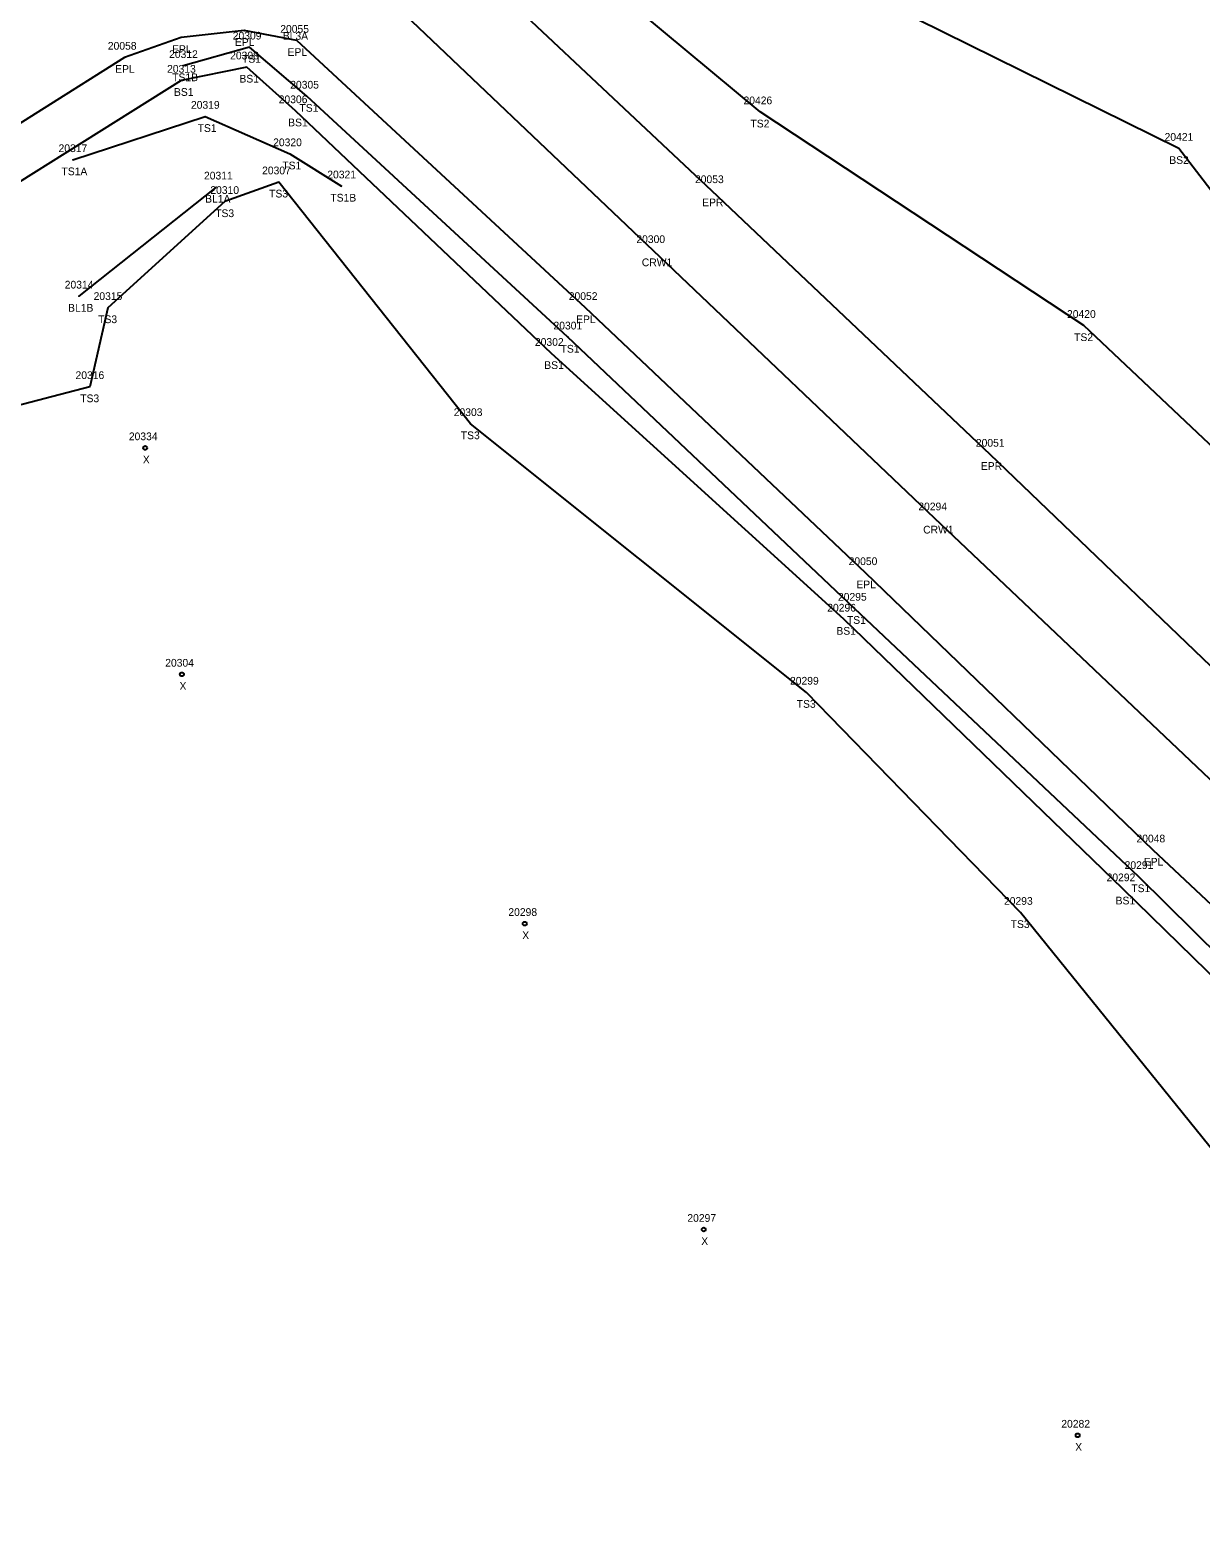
# Model space of a CAD drawing. Extents: x 1813127 to 1814107, y 1178171 to 1179078.
# Drawn here: x 1813803.8 to 1813955.3, y 1178426.8 to 1178622 of the extents above; entities that cross this region are included whole.
import ezdxf

# ---------------------------------------------------------------- set-up
doc = ezdxf.new("R2010")
doc.units = 0
for name, color, linetype in [('RD_DTM_BkLn1', 7, 'Continuous'), ('RD_DTM_BkLn2', 7, 'Continuous'), ('RD_EX_Road', 7, 'Continuous'), ('RD_EX_Road_txCode', 7, 'Continuous'), ('RD_SMD_Locator', 7, 'Continuous'), ('RD_SMD_Misc', 7, 'Continuous')]:
    doc.layers.add(name, color=color, linetype=linetype)

msp = doc.modelspace()

# ---------------------------------------------------------------- linework, layer by layer
at = {"layer": 'RD_DTM_BkLn1'}
msp.add_line((1813827.85, 1178601.7), (1813810.09, 1178587.58), dxfattribs=at)
msp.add_lwpolyline([(1814069.63, 1178419.56), (1814043.03, 1178443.95), (1814031.76, 1178453.98), (1813994.68, 1178489.07), (1813958.14, 1178523.5), (1813920.87, 1178558.86), (1813884.46, 1178593.47), (1813847.15, 1178628.98), (1813831.28, 1178643.33), (1813810.03, 1178662.5), (1813772.7, 1178693.86)], dxfattribs=at)
at = {"layer": 'RD_DTM_BkLn2'}
for points in [[(1814080.77, 1178431.89), (1814053.55, 1178456.53), (1814053.55, 1178456.53), (1814043.11, 1178466.04), (1814008.23, 1178502.68), (1813981.17, 1178545.08), (1813940.17, 1178583.78), (1813898.27, 1178611.44), (1813860.48, 1178642.94), (1813824.26, 1178675.11), (1813790.56, 1178704.96), (1813785.53, 1178702.33), (1813780.61, 1178703.45)], [(1814084.95, 1178436.37), (1814047.91, 1178471.1), (1814016.08, 1178513.45), (1813993.35, 1178553.48), (1813952.47, 1178606.71), (1813860.87, 1178652.01), (1813829.57, 1178687.07), (1813824.98, 1178702.29)], [(1814016.37, 1178444.99), (1813983.01, 1178477.16), (1813947.31, 1178512.42), (1813910.48, 1178547.16), (1813873.41, 1178582.28), (1813839.61, 1178613.47), (1813832.17, 1178619.82), (1813823.6, 1178617.43)], [(1814014.78, 1178443.42), (1813981.68, 1178475.25), (1813945.25, 1178510.83), (1813909.11, 1178545.75), (1813871.28, 1178580.16), (1813838.14, 1178611.58), (1813831.82, 1178617.25), (1813823.34, 1178615.53), (1813787.27, 1178592.92)], [(1813809.29, 1178605.25), (1813826.43, 1178610.86), (1813837.39, 1178606.01), (1813844.08, 1178601.84)], [(1813893.16, 1178338.84), (1813921.32, 1178364.43), (1813929.94, 1178352.15), (1813936.66, 1178353.94), (1813964.13, 1178381.53), (1813993.38, 1178417.59), (1814007.74, 1178441.51), (1813972.38, 1178457.8), (1813931.97, 1178507.78), (1813904.27, 1178536.29), (1813860.78, 1178571.07), (1813835.97, 1178602.37), (1813828.98, 1178599.83), (1813813.84, 1178586.1), (1813811.52, 1178575.86), (1813773.95, 1178566.06)]]:
    msp.add_lwpolyline(points, dxfattribs=at)
at = {"layer": 'RD_EX_Road'}
for points in [[(1814076.45, 1178427.4), (1814038.86, 1178461.87), (1814001.83, 1178496.62), (1813965.15, 1178531.54), (1813928.08, 1178567.1), (1813892.01, 1178601.23), (1813854.54, 1178636.51), (1813817.44, 1178670.03), (1813779.87, 1178701.64)], [(1813829.87, 1178208.6), (1813830.81, 1178209.56), (1813845.51, 1178227.94), (1813874.69, 1178258.74), (1813910.02, 1178295.38), (1813943.63, 1178333.84), (1813974.31, 1178373.09), (1814001.91, 1178410.56), (1814011.9, 1178425.95), (1814015.58, 1178434.3), (1814016.71, 1178442.08), (1814017.03, 1178447.13), (1814015.19, 1178453.67), (1813986.47, 1178480.85), (1813949.15, 1178515.86), (1813911.94, 1178551.77), (1813875.67, 1178586.1), (1813838.32, 1178620.7), (1813831.51, 1178622), (1813823.35, 1178621.08), (1813815.99, 1178618.51), (1813795.14, 1178605.39)]]:
    msp.add_lwpolyline(points, dxfattribs=at)
at = {"layer": 'RD_SMD_Locator'}
for centre, radius in [((1813823.35, 1178621.08), 0.001), ((1813831.51, 1178622), 0.001), ((1813838.32, 1178620.7), 0.001), ((1813832.17, 1178619.82), 0.001), ((1813815.99, 1178618.51), 0.001), ((1813823.6, 1178617.43), 0.001), ((1813831.82, 1178617.25), 0.001), ((1813823.34, 1178615.53), 0.001), ((1813839.61, 1178613.47), 0.001), ((1813826.43, 1178610.86), 0.001), ((1813838.14, 1178611.58), 0.001), ((1813898.27, 1178611.44), 0.001), ((1813809.29, 1178605.25), 0.001), ((1813837.39, 1178606.01), 0.001), ((1813952.47, 1178606.71), 0.001), ((1813827.85, 1178601.7), 0.001), ((1813835.97, 1178602.37), 0.001), ((1813844.08, 1178601.84), 0.001), ((1813892.01, 1178601.23), 0.001), ((1813828.98, 1178599.83), 0.001), ((1813884.46, 1178593.47), 0.001), ((1813810.09, 1178587.58), 0.001), ((1813813.84, 1178586.1), 0.001), ((1813875.67, 1178586.1), 0.001), ((1813940.17, 1178583.78), 0.001), ((1813873.41, 1178582.28), 0.001), ((1813871.28, 1178580.16), 0.001), ((1813811.52, 1178575.86), 0.001), ((1813860.78, 1178571.07), 0.001), ((1813818.68, 1178567.94), 0.25), ((1813928.08, 1178567.1), 0.001), ((1813920.87, 1178558.86), 0.001), ((1813911.94, 1178551.77), 0.001), ((1813910.48, 1178547.16), 0.001), ((1813909.11, 1178545.75), 0.001), ((1813823.43, 1178538.62), 0.25), ((1813904.27, 1178536.29), 0.001), ((1813949.15, 1178515.86), 0.001), ((1813947.31, 1178512.42), 0.001), ((1813945.25, 1178510.83), 0.001), ((1813931.97, 1178507.78), 0.001), ((1813867.81, 1178506.34), 0.25), ((1813890.98, 1178466.73), 0.25), ((1813939.39, 1178440.08), 0.25)]:
    msp.add_circle(centre, radius, dxfattribs=at)

# ---------------------------------------------------------------- texts
at = {"layer": 'RD_EX_Road_txCode'}
for s, p in [('20055', (1813836.16, 1178621.7)), ('20058', (1813813.84, 1178619.51)), ('EPL', (1813830.3, 1178620)), ('EPL', (1813822.15, 1178619.08)), ('EPL', (1813837.11, 1178618.7)), ('EPL', (1813814.79, 1178616.51)), ('20053', (1813889.85, 1178602.23)), ('EPR', (1813890.78, 1178599.23)), ('20052', (1813873.51, 1178587.1)), ('EPL', (1813874.46, 1178584.1)), ('20051', (1813926.21, 1178568.1)), ('EPR', (1813926.86, 1178565.1)), ('20050', (1813909.74, 1178552.77)), ('EPL', (1813910.74, 1178549.77)), ('20048', (1813947, 1178516.86)), ('EPL', (1813947.95, 1178513.86))]:
    msp.add_text(s, height=1, dxfattribs=at).set_placement(p)
at = {"layer": 'RD_SMD_Misc'}
for s, p in [('20309', (1813830.01, 1178620.82)), ('BL3A', (1813836.49, 1178620.79)), ('20312', (1813821.77, 1178618.43)), ('20308', (1813829.67, 1178618.25)), ('TS1', (1813831.21, 1178617.82)), ('20313', (1813821.51, 1178616.53)), ('TS1B', (1813822.17, 1178615.43)), ('BS1', (1813830.88, 1178615.25)), ('20305', (1813837.45, 1178614.47)), ('BS1', (1813822.4, 1178613.53)), ('20319', (1813824.6, 1178611.86)), ('20306', (1813835.96, 1178612.58)), ('20426', (1813896.13, 1178612.44)), ('TS1', (1813838.65, 1178611.47)), ('TS1', (1813825.47, 1178608.86)), ('BS1', (1813837.19, 1178609.58)), ('TS2', (1813897.03, 1178609.44)), ('20317', (1813807.46, 1178606.25)), ('20320', (1813835.24, 1178607.01)), ('20421', (1813950.64, 1178607.71)), ('TS1', (1813836.43, 1178604.01)), ('BS2', (1813951.25, 1178604.71)), ('TS1A', (1813807.84, 1178603.25)), ('20311', (1813826.29, 1178602.7)), ('20307', (1813833.81, 1178603.37)), ('20321', (1813842.25, 1178602.84)), ('20310', (1813827.11, 1178600.83)), ('TS3', (1813834.72, 1178600.37)), ('BL1A', (1813826.44, 1178599.7)), ('TS1B', (1813842.65, 1178599.84)), ('TS3', (1813827.74, 1178597.83)), ('20300', (1813882.26, 1178594.47)), ('CRW1', (1813882.97, 1178591.47)), ('20314', (1813808.26, 1178588.58)), ('20315', (1813812, 1178587.1)), ('BL1B', (1813808.7, 1178585.58)), ('20420', (1813938.01, 1178584.78)), ('TS3', (1813812.59, 1178584.1)), ('20301', (1813871.53, 1178583.28)), ('20302', (1813869.13, 1178581.16)), ('TS2', (1813938.93, 1178581.78)), ('TS1', (1813872.45, 1178580.28)), ('20316', (1813809.66, 1178576.86)), ('BS1', (1813870.34, 1178578.16)), ('TS3', (1813810.27, 1178573.86)), ('20303', (1813858.62, 1178572.07)), ('20334', (1813816.56, 1178568.94)), ('TS3', (1813859.53, 1178569.07)), ('X', (1813818.37, 1178565.94)), ('20294', (1813918.76, 1178559.86)), ('CRW1', (1813919.39, 1178556.86)), ('20295', (1813908.36, 1178548.16)), ('20296', (1813906.97, 1178546.75)), ('BS1', (1813908.16, 1178543.75)), ('TS1', (1813909.52, 1178545.16)), ('20304', (1813821.27, 1178539.62)), ('X', (1813823.12, 1178536.62)), ('20299', (1813902.15, 1178537.29)), ('TS3', (1813903.02, 1178534.29)), ('20291', (1813945.47, 1178513.42)), ('20292', (1813943.13, 1178511.83)), ('TS1', (1813946.34, 1178510.42)), ('20293', (1813929.85, 1178508.78)), ('BS1', (1813944.3, 1178508.83)), ('20298', (1813865.69, 1178507.34)), ('X', (1813867.49, 1178504.34)), ('TS3', (1813930.72, 1178505.78)), ('20297', (1813888.86, 1178467.73)), ('X', (1813890.66, 1178464.73)), ('20282', (1813937.27, 1178441.08)), ('X', (1813939.07, 1178438.08))]:
    msp.add_text(s, height=1, dxfattribs=at).set_placement(p)

doc.saveas('drawing.dxf')
